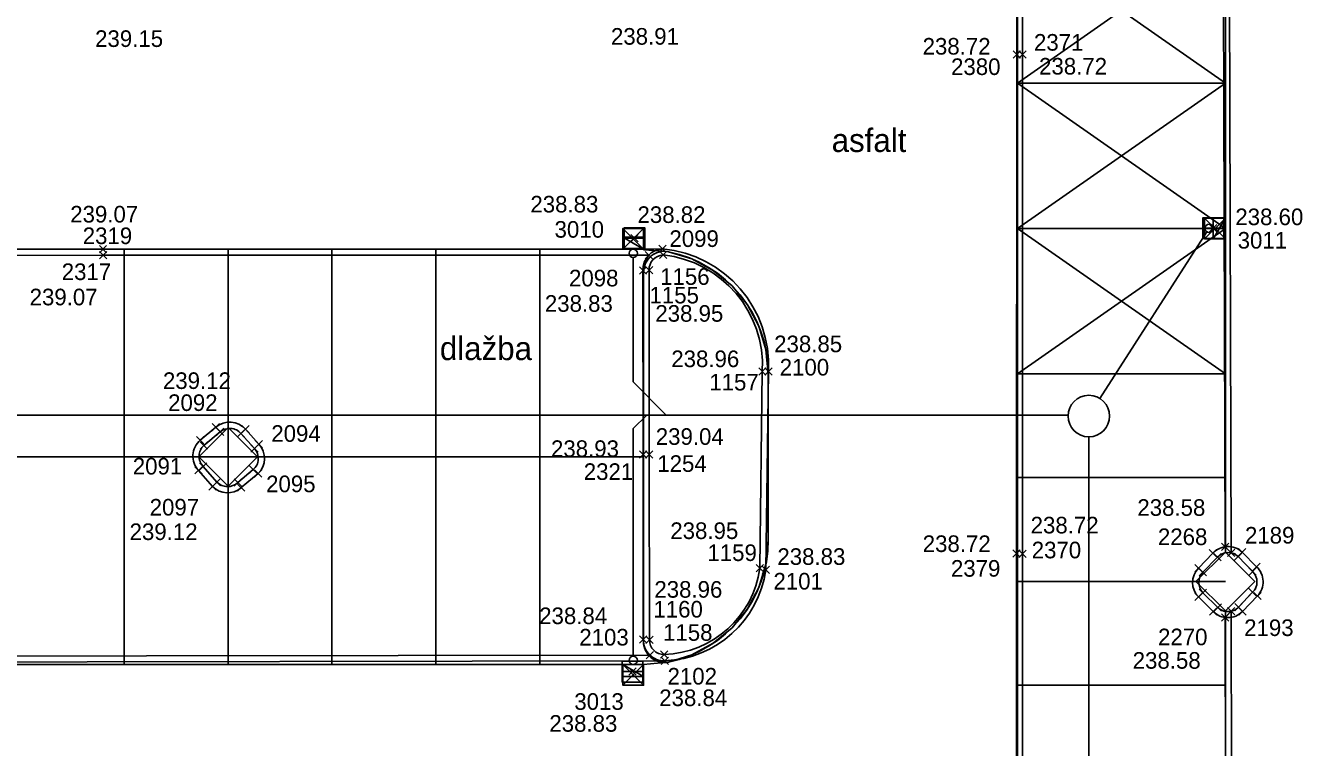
# Model space of a CAD drawing. Extents: x -264222 to -263676, y -1242344 to -1242060.
# Drawn here: x -264149.44 to -264118.71, y -1242214.48 to -1242197.1 of the extents above; entities that cross this region are included whole.
import ezdxf

# ---------------------------------------------------------------- set-up
doc = ezdxf.new("R2010")
doc.units = 0
for name, color, linetype in [('BODY_CISLO', 7, 'Continuous'), ('BODY_SYMBOL', 7, 'Continuous'), ('BODY_VYSKA', 7, 'Continuous'), ('BODY_VYSKY_UV', 7, 'Continuous'), ('KOORDINACNA_SITUACIA_DSP', 7, 'Continuous'), ('POPIS', 7, 'Continuous'), ('PROJEKT_DRS_OBRUBNIKY_KOMUNIKACIE', 7, 'Continuous'), ('PROJEKT_DRS_TDZ_VODOROVNE', 7, 'Continuous'), ('PROJEKT_DRS_UV_STAVBY', 7, 'Continuous'), ('SO_20-3_OBRUBNIKY_DOLNA_HRANA', 7, 'Continuous'), ('SO_20-3_OBRUBNIKY_HORNA_HRANA', 7, 'Continuous'), ('ULICNA_VPUST_POKLOP', 7, 'Continuous')]:
    doc.layers.add(name, color=color, linetype=linetype)

msp = doc.modelspace()

# ---------------------------------------------------------------- linework, layer by layer
at = {"layer": 'BODY_SYMBOL'}
for p, q in [((-264125.678, -1242197.886), (-264125.502, -1242197.71)), ((-264125.502, -1242197.886), (-264125.678, -1242197.71)), ((-264125.535, -1242197.885), (-264125.359, -1242197.709)), ((-264125.359, -1242197.885), (-264125.535, -1242197.709)), ((-264120.946, -1242202.064), (-264120.77, -1242201.888)), ((-264120.77, -1242202.064), (-264120.946, -1242201.888)), ((-264134.875, -1242202.308), (-264134.699, -1242202.132)), ((-264134.699, -1242202.308), (-264134.875, -1242202.132)), ((-264147.666, -1242202.573), (-264147.49, -1242202.397)), ((-264147.49, -1242202.573), (-264147.666, -1242202.397)), ((-264147.664, -1242202.716), (-264147.488, -1242202.54)), ((-264147.488, -1242202.716), (-264147.664, -1242202.54)), ((-264134.53, -1242202.713), (-264134.354, -1242202.537)), ((-264134.354, -1242202.713), (-264134.53, -1242202.537)), ((-264134.198, -1242202.564), (-264134.022, -1242202.388)), ((-264134.022, -1242202.564), (-264134.198, -1242202.388)), ((-264134.185, -1242202.709), (-264134.009, -1242202.533)), ((-264134.009, -1242202.709), (-264134.185, -1242202.533)), ((-264134.671, -1242203.081), (-264134.495, -1242202.905)), ((-264134.495, -1242203.081), (-264134.671, -1242202.905)), ((-264134.524, -1242203.079), (-264134.348, -1242202.903)), ((-264134.348, -1242203.079), (-264134.524, -1242202.903)), ((-264131.799, -1242205.515), (-264131.623, -1242205.339)), ((-264131.623, -1242205.515), (-264131.799, -1242205.339)), ((-264131.654, -1242205.517), (-264131.478, -1242205.341)), ((-264131.478, -1242205.517), (-264131.654, -1242205.341)), ((-264144.95, -1242206.858), (-264144.774, -1242206.682)), ((-264144.774, -1242206.858), (-264144.95, -1242206.682)), ((-264144.843, -1242206.967), (-264144.667, -1242206.791)), ((-264144.667, -1242206.967), (-264144.843, -1242206.791)), ((-264144.349, -1242207.008), (-264144.173, -1242206.832)), ((-264144.173, -1242207.008), (-264144.349, -1242206.832)), ((-264144.236, -1242206.907), (-264144.06, -1242206.731)), ((-264144.06, -1242206.907), (-264144.236, -1242206.731)), ((-264145.325, -1242207.169), (-264145.149, -1242206.993)), ((-264145.149, -1242207.169), (-264145.325, -1242206.993)), ((-264145.24, -1242207.295), (-264145.064, -1242207.119)), ((-264145.064, -1242207.295), (-264145.24, -1242207.119)), ((-264143.915, -1242207.265), (-264143.739, -1242207.089)), ((-264143.739, -1242207.265), (-264143.915, -1242207.089)), ((-264144.019, -1242207.372), (-264143.843, -1242207.196)), ((-264143.843, -1242207.372), (-264144.019, -1242207.196)), ((-264134.669, -1242207.515), (-264134.493, -1242207.339)), ((-264134.493, -1242207.515), (-264134.669, -1242207.339)), ((-264134.521, -1242207.512), (-264134.345, -1242207.336)), ((-264134.345, -1242207.512), (-264134.521, -1242207.336)), ((-264145.37, -1242207.895), (-264145.194, -1242207.719)), ((-264145.194, -1242207.895), (-264145.37, -1242207.719)), ((-264145.256, -1242207.799), (-264145.08, -1242207.623)), ((-264145.08, -1242207.799), (-264145.256, -1242207.623)), ((-264144.05, -1242207.878), (-264143.874, -1242207.702)), ((-264143.874, -1242207.878), (-264144.05, -1242207.702)), ((-264143.935, -1242207.974), (-264143.759, -1242207.798)), ((-264143.759, -1242207.974), (-264143.935, -1242207.798)), ((-264145.028, -1242208.281), (-264144.852, -1242208.105)), ((-264144.852, -1242208.281), (-264145.028, -1242208.105)), ((-264144.923, -1242208.177), (-264144.747, -1242208.001)), ((-264144.747, -1242208.177), (-264144.923, -1242208.001)), ((-264144.422, -1242208.188), (-264144.246, -1242208.012)), ((-264144.246, -1242208.188), (-264144.422, -1242208.012)), ((-264144.341, -1242208.312), (-264144.165, -1242208.136)), ((-264144.165, -1242208.312), (-264144.341, -1242208.136)), ((-264120.664, -1242209.735), (-264120.488, -1242209.559)), ((-264120.488, -1242209.735), (-264120.664, -1242209.559)), ((-264125.681, -1242209.898), (-264125.505, -1242209.722)), ((-264125.505, -1242209.898), (-264125.681, -1242209.722)), ((-264125.536, -1242209.902), (-264125.36, -1242209.726)), ((-264125.36, -1242209.902), (-264125.536, -1242209.726)), ((-264120.957, -1242209.891), (-264120.781, -1242209.715)), ((-264120.781, -1242209.891), (-264120.957, -1242209.715)), ((-264120.847, -1242209.984), (-264120.671, -1242209.808)), ((-264120.671, -1242209.984), (-264120.847, -1242209.808)), ((-264120.52, -1242209.884), (-264120.344, -1242209.708)), ((-264120.344, -1242209.884), (-264120.52, -1242209.708)), ((-264120.345, -1242209.973), (-264120.169, -1242209.797)), ((-264120.169, -1242209.973), (-264120.345, -1242209.797)), ((-264120.252, -1242209.862), (-264120.076, -1242209.686)), ((-264120.076, -1242209.862), (-264120.252, -1242209.686)), ((-264131.857, -1242210.251), (-264131.681, -1242210.075)), ((-264131.681, -1242210.251), (-264131.857, -1242210.075)), ((-264131.714, -1242210.292), (-264131.538, -1242210.116)), ((-264131.538, -1242210.292), (-264131.714, -1242210.116)), ((-264121.305, -1242210.253), (-264121.129, -1242210.077)), ((-264121.129, -1242210.253), (-264121.305, -1242210.077)), ((-264121.195, -1242210.345), (-264121.019, -1242210.169)), ((-264121.019, -1242210.345), (-264121.195, -1242210.169)), ((-264119.999, -1242210.334), (-264119.823, -1242210.158)), ((-264119.823, -1242210.334), (-264119.999, -1242210.158)), ((-264119.903, -1242210.217), (-264119.727, -1242210.041)), ((-264119.727, -1242210.217), (-264119.903, -1242210.041)), ((-264121.302, -1242210.941), (-264121.126, -1242210.765)), ((-264121.126, -1242210.941), (-264121.302, -1242210.765)), ((-264121.195, -1242210.842), (-264121.019, -1242210.666)), ((-264121.019, -1242210.842), (-264121.195, -1242210.666)), ((-264120.003, -1242210.829), (-264119.827, -1242210.653)), ((-264119.827, -1242210.829), (-264120.003, -1242210.653)), ((-264119.884, -1242210.92), (-264119.708, -1242210.744)), ((-264119.708, -1242210.92), (-264119.884, -1242210.744)), ((-264120.946, -1242211.295), (-264120.77, -1242211.119)), ((-264120.77, -1242211.295), (-264120.946, -1242211.119)), ((-264120.84, -1242211.194), (-264120.664, -1242211.018)), ((-264120.664, -1242211.194), (-264120.84, -1242211.018)), ((-264120.514, -1242211.287), (-264120.338, -1242211.111)), ((-264120.338, -1242211.287), (-264120.514, -1242211.111)), ((-264120.338, -1242211.187), (-264120.162, -1242211.011)), ((-264120.162, -1242211.187), (-264120.338, -1242211.011)), ((-264120.245, -1242211.296), (-264120.069, -1242211.12)), ((-264120.069, -1242211.296), (-264120.245, -1242211.12)), ((-264120.661, -1242211.436), (-264120.485, -1242211.26)), ((-264120.485, -1242211.436), (-264120.661, -1242211.26)), ((-264134.664, -1242211.97), (-264134.488, -1242211.794)), ((-264134.488, -1242211.97), (-264134.664, -1242211.794)), ((-264134.514, -1242211.978), (-264134.338, -1242211.802)), ((-264134.338, -1242211.978), (-264134.514, -1242211.802)), ((-264134.506, -1242212.343), (-264134.33, -1242212.167)), ((-264134.33, -1242212.343), (-264134.506, -1242212.167)), ((-264134.161, -1242212.329), (-264133.985, -1242212.153)), ((-264133.985, -1242212.329), (-264134.161, -1242212.153)), ((-264134.143, -1242212.479), (-264133.967, -1242212.303)), ((-264133.967, -1242212.479), (-264134.143, -1242212.303)), ((-264134.925, -1242212.741), (-264134.749, -1242212.565)), ((-264134.749, -1242212.741), (-264134.925, -1242212.565))]:
    msp.add_line(p, q, dxfattribs=at)
at = {"layer": 'KOORDINACNA_SITUACIA_DSP'}
for p, q in [((-264120.568, -1242192.189), (-264120.568, -1242209.775)), ((-264120.858, -1242202.232), (-264120.858, -1242201.732)), ((-264120.858, -1242201.732), (-264120.568, -1242201.732)), ((-264120.858, -1242202.232), (-264120.568, -1242201.732)), ((-264120.858, -1242202.232), (-264120.568, -1242201.732)), ((-264120.568, -1242201.732), (-264120.858, -1242201.732)), ((-264120.858, -1242201.732), (-264120.858, -1242202.232)), ((-264120.568, -1242201.732), (-264120.568, -1242202.232)), ((-264135.068, -1242202.192), (-264134.568, -1242202.192)), ((-264135.068, -1242202.482), (-264135.068, -1242202.192)), ((-264135.068, -1242202.192), (-264134.568, -1242202.482)), ((-264135.068, -1242202.192), (-264134.568, -1242202.482)), ((-264134.568, -1242202.192), (-264135.068, -1242202.192)), ((-264134.568, -1242202.192), (-264134.568, -1242202.482)), ((-264134.568, -1242202.482), (-264134.568, -1242202.192)), ((-264121.012, -1242202.066), (-264123.585, -1242206.079)), ((-264120.568, -1242202.232), (-264120.858, -1242202.232)), ((-264134.568, -1242202.482), (-264135.068, -1242202.482)), ((-264134.818, -1242202.682), (-264134.818, -1242205.68)), ((-264134.568, -1242203.033), (-264134.568, -1242211.932)), ((-264131.568, -1242209.482), (-264131.568, -1242205.482)), ((-264134.818, -1242205.68), (-264134.023, -1242206.476)), ((-264176.824, -1242206.476), (-264124.354, -1242206.476)), ((-264134.818, -1242206.801), (-264134.493, -1242206.476)), ((-264134.818, -1242212.282), (-264134.818, -1242206.801)), ((-264123.854, -1242207), (-264123.854, -1242236.976)), ((-264120.568, -1242211.189), (-264120.568, -1242219.774)), ((-264135.068, -1242212.482), (-264134.568, -1242212.482)), ((-264135.068, -1242212.772), (-264135.068, -1242212.482)), ((-264135.068, -1242212.482), (-264134.568, -1242212.772)), ((-264135.068, -1242212.482), (-264134.568, -1242212.772)), ((-264134.568, -1242212.482), (-264135.068, -1242212.482)), ((-264134.568, -1242212.482), (-264134.568, -1242212.772)), ((-264134.568, -1242212.772), (-264134.568, -1242212.482)), ((-264134.568, -1242212.772), (-264135.068, -1242212.772))]:
    msp.add_line(p, q, dxfattribs=at)
for points in [[(-264143.861, -1242207.482), (-264144.568, -1242206.775), (-264145.275, -1242207.482), (-264144.568, -1242208.189)], [(-264120.568, -1242209.775), (-264119.861, -1242210.482), (-264120.568, -1242211.189), (-264121.275, -1242210.482)]]:
    msp.add_lwpolyline(points, close=True, dxfattribs=at)
for centre, radius in [((-264120.958, -1242201.982), 0.1), ((-264134.818, -1242202.582), 0.1), ((-264123.854, -1242206.5), 0.5), ((-264134.818, -1242212.382), 0.1)]:
    msp.add_circle(centre, radius, dxfattribs=at)
for centre, radius, start, end in [((-264134.068, -1242203.033), 0.5, 78.463, 180), ((-264134.568, -1242205.482), 3, 0, 78.463), ((-264134.568, -1242209.482), 3, 281.537, 0), ((-264134.068, -1242211.932), 0.5, 180, 281.537)]:
    msp.add_arc(centre, radius, start, end, dxfattribs=at)
at = {"layer": 'PROJEKT_DRS_OBRUBNIKY_KOMUNIKACIE'}
for p, q in [((-264125.568, -1242270.982), (-264125.568, -1242191.482)), ((-264120.568, -1242192.189), (-264120.568, -1242209.775)), ((-264184.568, -1242202.482), (-264134.568, -1242202.482)), ((-264134.568, -1242202.495), (-264134.068, -1242202.533)), ((-264134.23, -1242202.56), (-264134.311, -1242202.596)), ((-264134.144, -1242202.539), (-264134.23, -1242202.56)), ((-264134.056, -1242202.533), (-264134.144, -1242202.539)), ((-264133.968, -1242202.543), (-264134.056, -1242202.533)), ((-264133.408, -1242202.716), (-264133.968, -1242202.543)), ((-264134.537, -1242202.859), (-264134.56, -1242202.945)), ((-264134.499, -1242202.779), (-264134.537, -1242202.859)), ((-264134.447, -1242202.707), (-264134.499, -1242202.779)), ((-264134.384, -1242202.645), (-264134.447, -1242202.707)), ((-264134.311, -1242202.596), (-264134.384, -1242202.645)), ((-264132.892, -1242202.994), (-264133.408, -1242202.716)), ((-264134.56, -1242202.945), (-264134.568, -1242203.033)), ((-264134.568, -1242203.033), (-264134.568, -1242207.482)), ((-264132.44, -1242203.367), (-264132.892, -1242202.994)), ((-264132.07, -1242203.821), (-264132.44, -1242203.367)), ((-264131.795, -1242204.338), (-264132.07, -1242203.821)), ((-264131.625, -1242204.899), (-264131.795, -1242204.338)), ((-264131.568, -1242205.482), (-264131.625, -1242204.899)), ((-264131.568, -1242209.482), (-264131.568, -1242205.482)), ((-264144.568, -1242206.775), (-264145.275, -1242207.482)), ((-264143.861, -1242207.482), (-264144.568, -1242206.775)), ((-264144.568, -1242206.775), (-264144.568, -1242208.189)), ((-264144.568, -1242208.189), (-264144.568, -1242206.775)), ((-264145.275, -1242207.482), (-264144.568, -1242208.189)), ((-264144.568, -1242208.189), (-264143.861, -1242207.482)), ((-264134.568, -1242207.482), (-264134.568, -1242211.932)), ((-264131.625, -1242210.065), (-264131.568, -1242209.482)), ((-264131.795, -1242210.626), (-264131.625, -1242210.065)), ((-264132.07, -1242211.144), (-264131.795, -1242210.626)), ((-264132.44, -1242211.598), (-264132.07, -1242211.144)), ((-264120.568, -1242211.189), (-264120.568, -1242219.774)), ((-264132.892, -1242211.971), (-264132.44, -1242211.598)), ((-264134.568, -1242211.932), (-264134.56, -1242212.02)), ((-264134.56, -1242212.02), (-264134.537, -1242212.105)), ((-264134.537, -1242212.105), (-264134.499, -1242212.185)), ((-264133.408, -1242212.249), (-264132.892, -1242211.971)), ((-264134.499, -1242212.185), (-264134.447, -1242212.257)), ((-264134.447, -1242212.257), (-264134.384, -1242212.319)), ((-264134.384, -1242212.319), (-264134.311, -1242212.369)), ((-264134.311, -1242212.369), (-264134.23, -1242212.405)), ((-264134.23, -1242212.405), (-264134.144, -1242212.426)), ((-264133.968, -1242212.422), (-264133.408, -1242212.249)), ((-264182.068, -1242212.482), (-264134.568, -1242212.482)), ((-264134.568, -1242212.482), (-264134.068, -1242212.432)), ((-264134.144, -1242212.426), (-264134.056, -1242212.432)), ((-264134.056, -1242212.432), (-264133.968, -1242212.422))]:
    msp.add_line(p, q, dxfattribs=at)
msp.add_lwpolyline([(-264120.568, -1242209.775), (-264119.861, -1242210.482), (-264120.568, -1242211.189), (-264121.275, -1242210.482), (-264120.568, -1242209.775)], dxfattribs=at)
at = {"layer": 'PROJEKT_DRS_TDZ_VODOROVNE'}
for p, q in [((-264125.568, -1242194.982), (-264120.568, -1242198.482)), ((-264125.568, -1242198.482), (-264120.568, -1242194.982)), ((-264125.568, -1242198.482), (-264120.568, -1242198.482)), ((-264125.568, -1242198.482), (-264120.568, -1242201.982)), ((-264125.568, -1242201.982), (-264120.568, -1242198.482)), ((-264125.568, -1242201.982), (-264120.568, -1242201.982)), ((-264125.568, -1242201.982), (-264120.568, -1242201.982)), ((-264125.568, -1242201.982), (-264120.568, -1242205.482)), ((-264125.568, -1242205.482), (-264120.568, -1242201.982)), ((-264147.068, -1242207.482), (-264147.068, -1242202.482)), ((-264144.568, -1242207.482), (-264144.568, -1242202.482)), ((-264142.068, -1242207.482), (-264142.068, -1242202.482)), ((-264139.568, -1242207.482), (-264139.568, -1242202.482)), ((-264137.068, -1242207.482), (-264137.068, -1242202.482)), ((-264125.568, -1242205.482), (-264120.568, -1242205.482)), ((-264134.568, -1242207.482), (-264184.568, -1242207.482)), ((-264134.568, -1242207.482), (-264175.568, -1242207.482)), ((-264147.068, -1242212.482), (-264147.068, -1242207.482)), ((-264144.568, -1242212.482), (-264144.568, -1242207.482)), ((-264142.068, -1242212.482), (-264142.068, -1242207.482)), ((-264139.568, -1242212.482), (-264139.568, -1242207.482)), ((-264137.068, -1242212.482), (-264137.068, -1242207.482)), ((-264125.568, -1242207.982), (-264120.568, -1242207.982)), ((-264125.568, -1242210.482), (-264120.568, -1242210.482)), ((-264125.568, -1242212.982), (-264120.568, -1242212.982))]:
    msp.add_line(p, q, dxfattribs=at)
at = {"layer": 'PROJEKT_DRS_UV_STAVBY'}
for points in [[(-264121.068, -1242202.232), (-264121.068, -1242201.732), (-264120.568, -1242201.732), (-264120.568, -1242202.232), (-264121.068, -1242202.232), (-264120.568, -1242201.732), (-264121.068, -1242201.732), (-264120.568, -1242202.232)], [(-264135.068, -1242202.482), (-264135.068, -1242201.982), (-264134.568, -1242201.982), (-264134.568, -1242202.482), (-264135.068, -1242202.482), (-264134.568, -1242201.982), (-264135.068, -1242201.982), (-264134.568, -1242202.482)], [(-264135.068, -1242212.982), (-264135.068, -1242212.482), (-264134.568, -1242212.482), (-264134.568, -1242212.982), (-264135.068, -1242212.982), (-264134.568, -1242212.482), (-264135.068, -1242212.482), (-264134.568, -1242212.982)]]:
    msp.add_lwpolyline(points, dxfattribs=at)
at = {"layer": 'SO_20-3_OBRUBNIKY_DOLNA_HRANA'}
for p, q in [((-264120.624, -1242192.346), (-264120.576, -1242209.647)), ((-264131.566, -1242205.429), (-264131.626, -1242210.204)), ((-264144.862, -1242206.77), (-264145.237, -1242207.081)), ((-264143.827, -1242207.177), (-264144.148, -1242206.819)), ((-264145.282, -1242207.807), (-264144.94, -1242208.193)), ((-264144.253, -1242208.224), (-264143.847, -1242207.886)), ((-264120.869, -1242209.803), (-264121.217, -1242210.165)), ((-264120.164, -1242209.774), (-264119.815, -1242210.129)), ((-264120.858, -1242211.207), (-264121.214, -1242210.853)), ((-264119.796, -1242210.832), (-264120.157, -1242211.208)), ((-264120.561, -1242219.617), (-264120.573, -1242211.348))]:
    msp.add_line(p, q, dxfattribs=at)
for points in [[(-264125.573, -1242270.915), (-264125.578, -1242264.895), (-264125.575, -1242255.299), (-264125.581, -1242244.324), (-264125.582, -1242233.844), (-264125.584, -1242219.84), (-264125.593, -1242209.81), (-264125.59, -1242197.798), (-264125.59, -1242191.484)], [(-264125.429, -1242270.662), (-264125.437, -1242264.9), (-264125.431, -1242255.315), (-264125.435, -1242244.34), (-264125.439, -1242233.845), (-264125.44, -1242219.841), (-264125.448, -1242209.814), (-264125.447, -1242197.797), (-264125.435, -1242191.484)], [(-264134.11, -1242202.476), (-264147.578, -1242202.485), (-264162.578, -1242202.5), (-264185.058, -1242202.528)], [(-264184.725, -1242202.666), (-264162.575, -1242202.645), (-264147.576, -1242202.628), (-264134.442, -1242202.625)], [(-264134.576, -1242211.882), (-264134.581, -1242207.427), (-264134.583, -1242202.993)], [(-264182.566, -1242212.438), (-264171.604, -1242212.447), (-264152.604, -1242212.425), (-264134.055, -1242212.391)], [(-264134.418, -1242212.255), (-264152.594, -1242212.281), (-264171.607, -1242212.3), (-264182.247, -1242212.302)]]:
    msp.add_lwpolyline(points, dxfattribs=at)
msp.add_arc((-264120.502, -1242210.139), 0.497, 47.1534, 137.5577, dxfattribs=at)
for centre, major_axis, ratio, start_param, end_param in [((-264134.087, -1242202.972), (0.042, -0.495), 0.999847, 3.103322, 4.66939), ((-264134.368, -1242205.27), (-2.411, 1.437), 0.999811, 3.622515, 5.157643), ((-264144.53, -1242207.153), (-0.422, -0.281), 0.999832, 3.272204, 4.839939), ((-264144.909, -1242207.466), (-0.172, 0.475), 0.999619, 0.358017, 1.963712), ((-264144.195, -1242207.521), (0.083, 0.497), 0.99979, 4.070392, 5.630202), ((-264144.581, -1242207.856), (0.32, -0.375), 0.999903, 4.760359, 6.304194), ((-264134.146, -1242209.848), (2.185, 1.305), 0.999639, 4.209977, 5.604479), ((-264120.866, -1242210.507), (-0.486, -0.066), 0.999983, 5.375522, 6.930743), ((-264120.157, -1242210.49), (0.054, 0.494), 0.999945, 4.063089, 5.634789), ((-264120.507, -1242210.857), (0.44, 0.229), 0.999981, 3.445247, 5.016187), ((-264134.074, -1242211.889), (0.498, -0.066), 0.999934, 3.258332, 4.88166)]:
    msp.add_ellipse(centre, major_axis=major_axis, ratio=ratio, start_param=start_param, end_param=end_param, dxfattribs=at)
at = {"layer": 'SO_20-3_OBRUBNIKY_HORNA_HRANA'}
for p, q in [((-264120.432, -1242209.796), (-264120.475, -1242192.159)), ((-264131.769, -1242210.163), (-264131.711, -1242205.427)), ((-264145.152, -1242207.207), (-264144.755, -1242206.879)), ((-264144.261, -1242206.92), (-264143.931, -1242207.284)), ((-264144.835, -1242208.089), (-264145.168, -1242207.711)), ((-264143.962, -1242207.79), (-264144.334, -1242208.1)), ((-264121.107, -1242210.257), (-264120.759, -1242209.896)), ((-264120.257, -1242209.885), (-264119.911, -1242210.246)), ((-264120.752, -1242211.106), (-264121.107, -1242210.754)), ((-264119.915, -1242210.741), (-264120.25, -1242211.099)), ((-264120.422, -1242219.757), (-264120.426, -1242211.199))]:
    msp.add_line(p, q, dxfattribs=at)
msp.add_lwpolyline([(-264134.436, -1242202.991), (-264134.433, -1242207.424), (-264134.426, -1242211.89)], dxfattribs=at)
for centre, major_axis, ratio, start_param, end_param in [((-264134.078, -1242202.978), (-0.009, -0.358), 0.999774, 3.220198, 4.773955), ((-264134.381, -1242205.28), (-2.264, 1.423), 0.999784, 3.647567, 5.166933), ((-264144.529, -1242207.145), (-0.339, -0.087), 0.998783, 3.590331, 5.167715), ((-264144.91, -1242207.467), (0.095, -0.342), 0.99945, 3.619553, 5.198199), ((-264144.197, -1242207.522), (0.046, 0.354), 0.998359, 3.992312, 5.570367), ((-264144.579, -1242207.848), (0.317, -0.153), 0.999063, 4.347989, 5.932368), ((-264120.502, -1242210.148), (-0.353, 0.07), 0.998931, 4.157914, 5.70111), ((-264134.149, -1242209.84), (2.075, 1.209), 0.999939, 4.216565, 5.620836), ((-264120.852, -1242210.506), (0.184, -0.304), 0.99963, 3.395005, 4.941577), ((-264120.147, -1242210.492), (-0.043, 0.338), 0.998999, 3.764131, 5.388805), ((-264120.504, -1242210.857), (0.35, -0.025), 0.999717, 4.00003, 5.592358), ((-264134.079, -1242211.894), (-0.3, 0.174), 0.999722, 0.512216, 2.112308)]:
    msp.add_ellipse(centre, major_axis=major_axis, ratio=ratio, start_param=start_param, end_param=end_param, dxfattribs=at)
at = {"layer": 'ULICNA_VPUST_POKLOP'}
for p, q in [((-264134.787, -1242202.22), (-264134.787, -1242202.22)), ((-264120.858, -1242201.976), (-264120.858, -1242201.976)), ((-264134.837, -1242212.653), (-264134.837, -1242212.653))]:
    msp.add_line(p, q, dxfattribs=at)
for points in [[(-264135.037, -1242202.22), (-264135.037, -1242201.97), (-264134.537, -1242201.97), (-264134.537, -1242202.47), (-264135.037, -1242202.47), (-264135.037, -1242202.22), (-264134.537, -1242202.22)], [(-264121.108, -1242201.976), (-264121.108, -1242201.726), (-264120.608, -1242201.726), (-264120.608, -1242202.226), (-264121.108, -1242202.226), (-264121.108, -1242201.976), (-264120.608, -1242201.976)], [(-264135.087, -1242212.653), (-264135.087, -1242212.403), (-264134.587, -1242212.403), (-264134.587, -1242212.903), (-264135.087, -1242212.903), (-264135.087, -1242212.653), (-264134.587, -1242212.653)]]:
    msp.add_lwpolyline(points, dxfattribs=at)

# ---------------------------------------------------------------- texts
at = {"layer": 'BODY_CISLO'}
for s, p in [('2371', (-264125.174, -1242197.703)), ('2380', (-264127.169, -1242198.289)), ('2319', (-264148.066, -1242202.36)), ('3010', (-264136.711, -1242202.206)), ('2099', (-264133.947, -1242202.429)), ('3011', (-264120.272, -1242202.468)), ('2317', (-264148.571, -1242203.225)), ('2098', (-264136.363, -1242203.378)), ('1156', (-264134.17, -1242203.341)), ('1155', (-264134.426, -1242203.789)), ('2100', (-264131.293, -1242205.524)), ('1157', (-264132.987, -1242205.884)), ('2092', (-264146.011, -1242206.378)), ('2094', (-264143.528, -1242207.12)), ('2091', (-264146.861, -1242207.907)), ('1254', (-264134.239, -1242207.844)), ('2321', (-264136.008, -1242208.038)), ('2095', (-264143.653, -1242208.333)), ('2097', (-264146.455, -1242208.895)), ('2268', (-264122.191, -1242209.606)), ('2189', (-264120.096, -1242209.57)), ('1159', (-264133.033, -1242209.99)), ('2370', (-264125.228, -1242209.925)), ('2379', (-264127.172, -1242210.367)), ('2101', (-264131.443, -1242210.676)), ('1160', (-264134.332, -1242211.351)), ('2193', (-264120.115, -1242211.796)), ('2103', (-264136.116, -1242212.024)), ('1158', (-264134.1, -1242211.911)), ('2270', (-264122.188, -1242212.018)), ('2102', (-264133.992, -1242212.964)), ('3013', (-264136.236, -1242213.573))]:
    msp.add_text(s, height=0.4, dxfattribs=at).set_placement(p)
at = {"layer": 'BODY_VYSKA'}
for s, p in [('239.15', (-264147.768, -1242197.614)), ('238.91', (-264135.354, -1242197.559)), ('238.72', (-264127.854, -1242197.798)), ('238.72', (-264125.051, -1242198.278)), ('239.07', (-264148.367, -1242201.84)), ('238.82', (-264134.715, -1242201.851)), ('239.07', (-264149.344, -1242203.834)), ('238.83', (-264136.944, -1242203.99)), ('238.95', (-264134.286, -1242204.229)), ('238.85', (-264131.426, -1242204.963)), ('238.96', (-264133.902, -1242205.322)), ('239.12', (-264146.136, -1242205.848)), ('239.04', (-264134.275, -1242207.193)), ('238.93', (-264136.797, -1242207.485)), ('238.58', (-264122.686, -1242208.902)), ('238.72', (-264125.254, -1242209.326)), ('239.12', (-264146.938, -1242209.485)), ('238.95', (-264133.926, -1242209.46)), ('238.72', (-264127.851, -1242209.773)), ('238.83', (-264131.349, -1242210.083)), ('238.96', (-264134.309, -1242210.873)), ('238.84', (-264137.081, -1242211.509)), ('238.58', (-264122.798, -1242212.583)), ('238.84', (-264134.192, -1242213.482))]:
    msp.add_text(s, height=0.4, dxfattribs=at).set_placement(p)
at = {"layer": 'BODY_VYSKY_UV'}
for s, p in [('238.83', (-264137.293, -1242201.599)), ('238.60', (-264120.328, -1242201.904)), ('238.83', (-264136.836, -1242214.1))]:
    msp.add_text(s, height=0.4, dxfattribs=at).set_placement(p)
at = {"layer": 'POPIS'}
msp.add_text('asfalt', height=0.5625, dxfattribs=at).set_placement((-264130.042, -1242200.143))
msp.add_text('dlažba', height=0.5625, rotation=360, dxfattribs=at).set_placement((-264139.471, -1242205.153))

doc.saveas('drawing.dxf')
